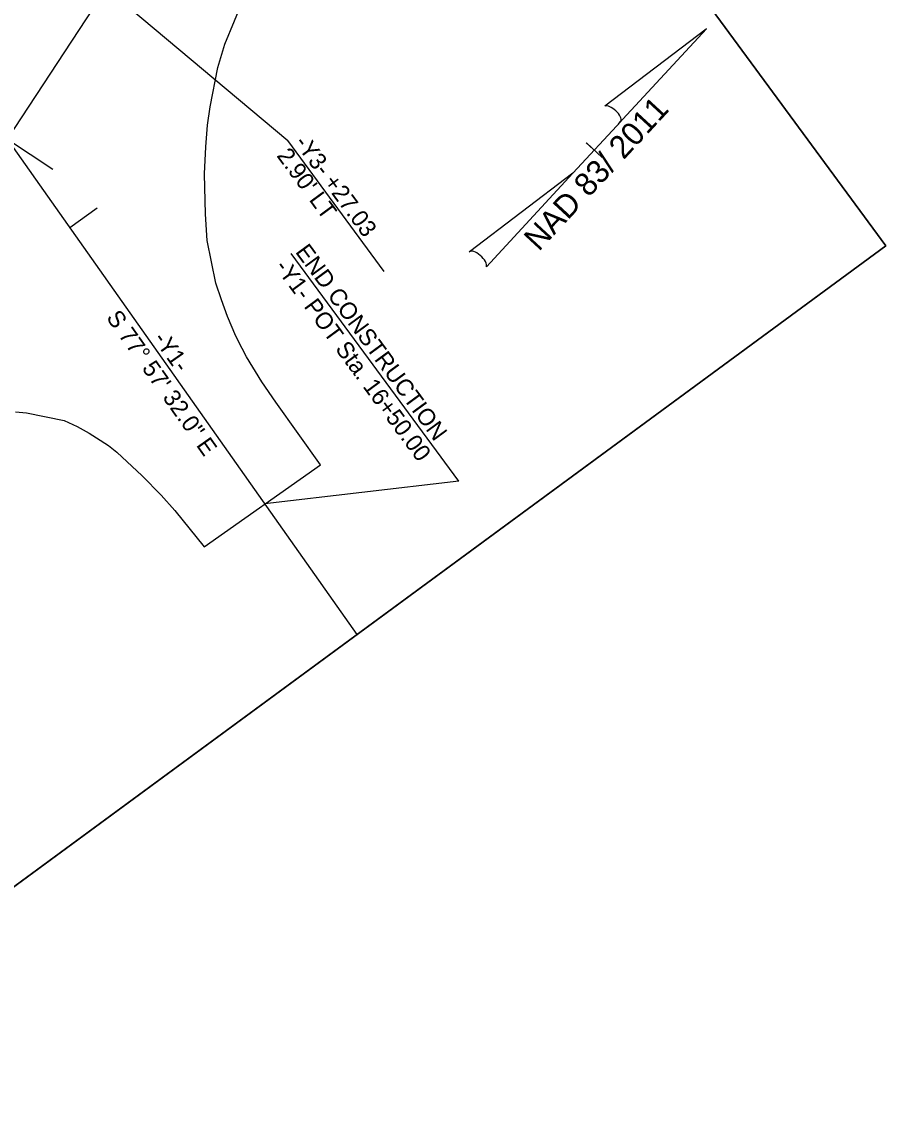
# Model space of a CAD drawing. Extents: x 1763480 to 1764420, y 711010 to 712012.
# Drawn here: x 1763855 to 1763983.9, y 711290.7 to 711453.1 of the extents above; entities that cross this region are included whole.
import ezdxf

# ---------------------------------------------------------------- set-up
doc = ezdxf.new("R2010")
doc.units = 0
for name, color, linetype in [('Old_Level_11', 7, 'Continuous'), ('Prop EOT', 7, 'Continuous'), ('Prop Grid Mask', 7, 'Continuous'), ('Prop Horizontal Alignment Direction Label', 7, 'Continuous'), ('Prop Horizontal Alignment Station Label', 7, 'Continuous'), ('Prop Horizontal Alignment Tick Large', 7, 'Continuous'), ('Prop Horizontal Alignment Tick Small', 7, 'Continuous'), ('Prop North Arrow NAD83 for Plan Sheets CELL', 7, 'Continuous'), ('Prop Rem of Exist Asph Pvmt', 7, 'Continuous'), ('Sheet Block Revision CELL', 7, 'Continuous')]:
    doc.layers.add(name, color=color, linetype=linetype)

msp = doc.modelspace()

# ---------------------------------------------------------------- linework, layer by layer
at = {"layer": 'Old_Level_11'}
msp.add_lwpolyline([(1763871.46, 711571.1), (1763982.56, 711419.98), (1763814.35, 711296.3), (1763703.24, 711447.42)], close=True, dxfattribs=at)
msp.add_lwpolyline([(1763871.46, 711571.1), (1763982.56, 711419.98), (1763814.35, 711296.3), (1763703.24, 711447.42)], close=True, dxfattribs=at)
msp.add_lwpolyline([(1763871.46, 711571.1), (1763982.56, 711419.98), (1763814.35, 711296.3), (1763703.24, 711447.42)], close=True, dxfattribs=at)
msp.add_lwpolyline([(1763871.46, 711571.1), (1763982.56, 711419.98), (1763814.35, 711296.3), (1763703.24, 711447.42)], close=True, dxfattribs=at)
at = {"layer": 'Prop EOT'}
for p, q in [((1763884.94, 711449.8), (1763891.9, 711466.49)), ((1763883.91, 711446.31), (1763884.94, 711449.8)), ((1763882.77, 711440.52), (1763883.91, 711446.31)), ((1763882.37, 711437.79), (1763882.77, 711440.52)), ((1763882.12, 711434.61), (1763882.37, 711437.79)), ((1763881.95, 711430.6), (1763882.12, 711434.61)), ((1763882.11, 711424.65), (1763881.95, 711430.6)), ((1763882.35, 711420.75), (1763882.11, 711424.65)), ((1763883.63, 711414.46), (1763882.35, 711420.75)), ((1763884.47, 711411.99), (1763883.63, 711414.46)), ((1763885.36, 711409.55), (1763884.47, 711411.99)), ((1763886.58, 711406.64), (1763885.36, 711409.55)), ((1763887.49, 711404.81), (1763886.58, 711406.64)), ((1763888.13, 711403.56), (1763887.49, 711404.81)), ((1763890.42, 711399.87), (1763888.13, 711403.56)), ((1763892.47, 711396.86), (1763890.42, 711399.87)), ((1763899.06, 711387.64), (1763892.47, 711396.86)), ((1763854.03, 711395.45), (1763855.64, 711395.32)), ((1763855.64, 711395.32), (1763861.21, 711394.18)), ((1763861.21, 711394.18), (1763863.12, 711393.3)), ((1763863.12, 711393.3), (1763864.92, 711392.29)), ((1763864.92, 711392.29), (1763866, 711391.62)), ((1763866, 711391.62), (1763867.77, 711390.48)), ((1763867.77, 711390.48), (1763869.01, 711389.5)), ((1763869.01, 711389.5), (1763872.71, 711385.98)), ((1763881.87, 711375.51), (1763899.06, 711387.64)), ((1763872.71, 711385.98), (1763875.54, 711383.14)), ((1763875.54, 711383.14), (1763877.57, 711380.9)), ((1763877.57, 711380.9), (1763881.87, 711375.51))]:
    msp.add_line(p, q, dxfattribs=at)
at = {"layer": 'Prop Grid Mask'}
for p in [(1763865.23, 711459.91), (1763908.49, 711416.17)]:
    msp.add_line(p, (1763894.25, 711435.54), dxfattribs=at)
at = {"layer": 'Prop Horizontal Alignment Station Label'}
msp.add_lwpolyline([(1763957.77, 711941.04), (1764052.94, 711811.6), (1764008.24, 711778.74), (1764295.85, 711387.56), (1764241.65, 711347.71), (1764301.88, 711263.14), (1763979.82, 711026.35), (1763792.92, 711280.55), (1763982.56, 711419.98), (1763871.46, 711571.1), (1763681.82, 711431.66), (1763535.55, 711630.61)], close=True, dxfattribs=at)
at = {"layer": 'Prop Horizontal Alignment Tick Large'}
msp.add_line((1763852.84, 711435.72), (1763859.53, 711431.33), dxfattribs=at)
at = {"layer": 'Prop Horizontal Alignment Tick Small'}
msp.add_line((1763862.03, 711422.7), (1763866.11, 711425.58), dxfattribs=at)
at = {"layer": 'Prop North Arrow NAD83 for Plan Sheets CELL'}
for p, q in [((1763941.05, 711440.65), (1763956.04, 711452.04)), ((1763956.05, 711452.03), (1763943.08, 711437.99)), ((1763956.05, 711452.03), (1763956.04, 711452.04)), ((1763956.05, 711452.03), (1763956.04, 711452.04)), ((1763936.34, 711430.7), (1763943.46, 711438.4)), ((1763943.08, 711437.99), (1763943.44, 711438.38)), ((1763938.32, 711435.2), (1763938.3, 711435.21)), ((1763939.36, 711434.23), (1763938.32, 711435.2)), ((1763938.33, 711435.18), (1763940.68, 711433.01)), ((1763936.34, 711430.7), (1763921.06, 711419.09)), ((1763923.59, 711416.87), (1763936.34, 711430.7))]:
    msp.add_line(p, q, dxfattribs=at)
for centre, start_param, end_param in [((1763942.13, 711439.38), 0.216388, 2.908219), ((1763922.26, 711417.89), 0.201328, 3.141593)]:
    msp.add_ellipse(centre, major_axis=(1.23, -1.16), ratio=0.461098, start_param=start_param, end_param=end_param, dxfattribs=at)
at = {"layer": 'Prop Rem of Exist Asph Pvmt'}
for q in [(1763894.76, 711418.85), (1763890.86, 711381.85)]:
    msp.add_line((1763919.48, 711385.23), q, dxfattribs=at)
at = {"layer": 'Sheet Block Revision CELL'}
for p, q in [((1763852.84, 711435.72), (1763908.53, 711520.67)), ((1763904.48, 711362.57), (1763796.29, 711515.83))]:
    msp.add_line(p, q, dxfattribs=at)

# ---------------------------------------------------------------- texts
at = {"layer": 'Prop Grid Mask'}
for s, p in [('-Y3- +27.03', (1763895.13, 711435.21)), ("2.90' LT", (1763892.51, 711433.29))]:
    msp.add_text(s, height=2.5, rotation=306.325, dxfattribs=at).set_placement(p)
at = {"layer": 'Prop Horizontal Alignment Direction Label'}
for s, rotation, p in [('S 77%%d 57\' 32.0" E', 305.2189, (1763867.34, 711409.36)), ('-Y1- ', 305.1238, (1763874.28, 711406.25))]:
    msp.add_text(s, height=2.5, rotation=rotation, dxfattribs=at).set_placement(p)
at = {"layer": 'Prop North Arrow NAD83 for Plan Sheets CELL'}
msp.add_text('NAD 83/ 2011', height=3.4, rotation=47.26, dxfattribs=at).set_placement((1763931.31, 711419.06))
at = {"layer": 'Prop Rem of Exist Asph Pvmt'}
for s, p in [('END CONSTRUCTION', (1763895.26, 711419.08)), ('-Y1- POT Sta. 16+50.00', (1763892.24, 711416.86))]:
    msp.add_text(s, height=2.5, rotation=306.325, dxfattribs=at).set_placement(p)

doc.saveas('drawing.dxf')
